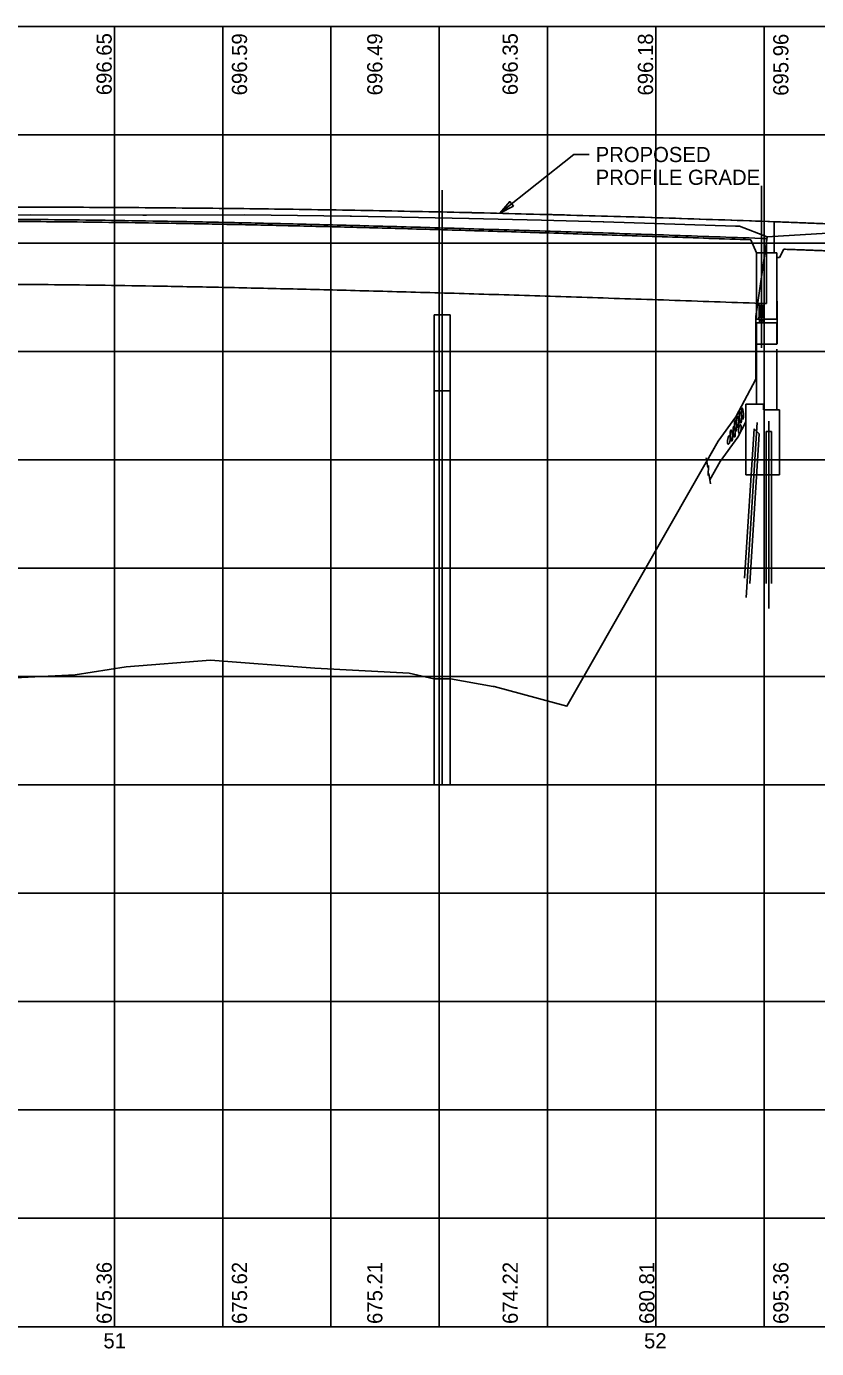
# Model space of a CAD drawing. Extents: x 991 to 1508, y 566 to 813.
# Drawn here: x 1183.7 to 1329.7, y 566 to 810 of the extents above; entities that cross this region are included whole.
import ezdxf

# ---------------------------------------------------------------- set-up
doc = ezdxf.new("R2010")
doc.units = 0
for name, color, linetype in [('BR_P_Brg_Pad_Object', 7, 'Continuous'), ('BR_P_Dia_Object', 7, 'Continuous'), ('BR_P_Gen_Approach_Slab', 7, 'Continuous'), ('BR_P_Gen_Phase_Construction', 7, 'Continuous'), ('BR_P_Gen_Waterproofing', 7, 'Continuous'), ('BR_P_Slab_Object', 7, 'Continuous'), ('BR_P_Sub_Object', 7, 'Continuous'), ('BR_X_Beam_Object', 7, 'Continuous'), ('BR_X_Brg_Centerline', 7, 'Continuous'), ('BR_X_Gen_Porous_Backfill', 7, 'Continuous'), ('BR_X_Gen_Slope_Protection', 7, 'Continuous'), ('BR_X_Sub_Const_Joint', 7, 'Continuous'), ('BR_X_Sub_Deep_Centerline', 7, 'Continuous'), ('BR_X_Sub_Deep_Object', 7, 'Continuous'), ('BR_X_Sub_Object', 7, 'Continuous'), ('Default', 7, 'Continuous'), ('PF_P_Grade_Line', 7, 'Continuous'), ('PF_P_Sta_Elev_Text', 7, 'Continuous'), ('PF_P_Text_Strip_Grades_20', 7, 'Continuous'), ('PF_X_Ground_Line', 7, 'Continuous'), ('PF_X_Text_Strip_Grade', 7, 'Continuous'), ('SC_Scratch1', 7, 'Continuous'), ('SH_Major_Grid_Line', 7, 'Continuous'), ('SH_Text', 7, 'Continuous')]:
    doc.layers.add(name, color=color, linetype=linetype)

msp = doc.modelspace()

# ---------------------------------------------------------------- linework, layer by layer
at = {"layer": 'BR_P_Brg_Pad_Object'}
for p, q in [((1320.04, 758.84), (1319.04, 758.84)), ((1319.04, 758.51), (1319.04, 758.84)), ((1320.04, 758.51), (1319.04, 758.51)), ((1319.12, 756.32), (1319.12, 758.51)), ((1319.2, 756.32), (1319.2, 758.51)), ((1319.87, 756.32), (1319.87, 758.51)), ((1319.95, 756.32), (1319.95, 758.51)), ((1320.04, 758.84), (1320.04, 758.51)), ((1320.04, 756.32), (1319.04, 756.32)), ((1319.04, 756.32), (1319.04, 755.98)), ((1320.12, 755.98), (1319.12, 755.98)), ((1319.16, 755.32), (1319.16, 755.98)), ((1319.91, 755.65), (1319.16, 755.65)), ((1319.99, 755.32), (1319.24, 755.32)), ((1319.91, 755.32), (1319.91, 755.98)), ((1320.04, 756.32), (1320.04, 755.98))]:
    msp.add_line(p, q, dxfattribs=at)
at = {"layer": 'BR_P_Dia_Object'}
for p, q in [((1318.62, 768.19), (1317.55, 770.61)), ((1318.62, 755.98), (1318.62, 768.19)), ((1321.87, 768.19), (1322.37, 768.19)), ((1322.37, 768.19), (1322.37, 755.98)), ((1318.62, 755.98), (1322.37, 755.98))]:
    msp.add_line(p, q, dxfattribs=at)
at = {"layer": 'BR_P_Gen_Approach_Slab'}
for p in [(1323.63, 768.88), (1322.37, 767.36)]:
    msp.add_line(p, (1322.87, 767.36), dxfattribs=at)
for points in [[(1321.87, 773.95), (1334.37, 773.49), (1346.87, 772.95)], [(1323.63, 768.88), (1331.31, 768.6), (1338.98, 768.28), (1346.87, 767.94)]]:
    msp.add_open_spline(points, degree=2, dxfattribs=at)
at = {"layer": 'BR_P_Gen_Phase_Construction'}
msp.add_line((1321.87, 768.19), (1318.62, 768.19), dxfattribs=at)
at = {"layer": 'BR_P_Gen_Waterproofing'}
msp.add_line((1322.45, 759.3), (1322.45, 751.33), dxfattribs=at)
at = {"layer": 'BR_P_Slab_Object'}
msp.add_line((1321.87, 773.95), (1321.87, 768.19), dxfattribs=at)
for points in [[(1030.21, 773.96), (1176.04, 779.36), (1321.87, 773.95)], [(1034.6, 770.62), (1128.92, 774.01), (1223.23, 774), (1317.55, 770.61)]]:
    msp.add_open_spline(points, degree=2, dxfattribs=at)
at = {"layer": 'BR_P_Sub_Object'}
for p, q in [((1318.62, 755.32), (1322.37, 755.32)), ((1318.62, 751.33), (1318.62, 755.32)), ((1322.37, 755.32), (1322.37, 751.33)), ((1318.62, 751.33), (1322.37, 751.33))]:
    msp.add_line(p, q, dxfattribs=at)
at = {"layer": 'BR_X_Beam_Object'}
for p, q in [((1320.45, 770.84), (1320.45, 758.84)), ((1259.04, 756.74), (1259.04, 670)), ((1262.04, 756.74), (1262.04, 670)), ((1318.63, 740.26), (1318.63, 751.33)), ((1322.38, 739.26), (1322.38, 750.46)), ((1316.63, 740.26), (1316.63, 727.26)), ((1322.88, 727.26), (1322.88, 739.26)), ((1316.42, 708.14), (1318.15, 735.75)), ((1317.39, 707.16), (1319.12, 734.78)), ((1320.38, 707.16), (1320.38, 735.26)), ((1321.38, 707.16), (1321.38, 735.26)), ((1316.63, 727.26), (1322.88, 727.26))]:
    msp.add_line(p, q, dxfattribs=at)
for points in [[(1309.43, 729.74), (1311.55, 733.44), (1314.77, 737.92), (1318.48, 744.88)], [(1316.63, 736.99), (1315.15, 734.21), (1311.92, 729.72), (1309.99, 726.34)]]:
    msp.add_lwpolyline(points, dxfattribs=at)
for points in [[(1031.63, 770.84), (1125.99, 774.38), (1220.35, 774.43), (1320.45, 770.84)], [(1031.63, 758.84), (1125.99, 762.38), (1220.35, 762.43), (1320.45, 758.84)]]:
    msp.add_open_spline(points, degree=2, dxfattribs=at)
at = {"layer": 'BR_X_Brg_Centerline'}
for p, q in [((1260.54, 670), (1260.54, 779.78)), ((1319.54, 750.66), (1319.54, 780.57))]:
    msp.add_line(p, q, dxfattribs=at)
at = {"layer": 'BR_X_Gen_Porous_Backfill'}
for points in [[(1316.17, 739.01), (1316.23, 738.41), (1316.21, 737.81), (1316.15, 737.57), (1316.05, 737.57), (1315.91, 737.99), (1315.84, 738.59), (1315.84, 739.19), (1315.9, 739.49), (1316, 739.55), (1316.11, 739.25), (1316.17, 738.95)], [(1314.86, 736.76), (1314.92, 736.16), (1314.91, 735.56), (1314.85, 735.32), (1314.74, 735.32), (1314.61, 735.74), (1314.53, 736.34), (1314.53, 736.94), (1314.59, 737.24), (1314.7, 737.3), (1314.8, 737), (1314.86, 736.7)], [(1315.26, 737.47), (1315.32, 736.87), (1315.31, 736.27), (1315.25, 736.03), (1315.14, 736.03), (1315.01, 736.45), (1314.93, 737.05), (1314.93, 737.65), (1314.99, 737.95), (1315.1, 738.01), (1315.2, 737.71), (1315.26, 737.41)], [(1315.76, 738.3), (1315.82, 737.7), (1315.81, 737.1), (1315.75, 736.86), (1315.64, 736.86), (1315.51, 737.28), (1315.43, 737.88), (1315.43, 738.48), (1315.49, 738.78), (1315.6, 738.84), (1315.7, 738.54), (1315.76, 738.24)], [(1314.1, 734.94), (1314.16, 734.34), (1314.15, 733.74), (1314.09, 733.5), (1313.98, 733.5), (1313.85, 733.92), (1313.77, 734.52), (1313.77, 735.12), (1313.83, 735.42), (1313.94, 735.48), (1314.04, 735.18), (1314.1, 734.88)], [(1314.6, 735.66), (1314.66, 735.06), (1314.65, 734.46), (1314.59, 734.22), (1314.48, 734.22), (1314.35, 734.64), (1314.27, 735.24), (1314.27, 735.84), (1314.33, 736.14), (1314.44, 736.2), (1314.54, 735.9), (1314.6, 735.6)], [(1315.64, 735.13), (1315.49, 734.89), (1315.34, 734.95), (1315.28, 735.19), (1315.28, 735.61), (1315.39, 736.15), (1315.54, 736.45), (1315.69, 736.45), (1315.76, 736.21), (1315.78, 735.79), (1315.7, 735.37), (1315.63, 735.13)], [(1313.61, 733.11), (1313.46, 732.87), (1313.31, 732.93), (1313.25, 733.17), (1313.25, 733.59), (1313.36, 734.13), (1313.51, 734.43), (1313.66, 734.43), (1313.73, 734.19), (1313.75, 733.77), (1313.67, 733.35), (1313.6, 733.11)]]:
    msp.add_lwpolyline(points, dxfattribs=at)
at = {"layer": 'BR_X_Gen_Slope_Protection'}
for p, q in [((1309.62, 728.58), (1309.33, 730.37)), ((1309.76, 728.94), (1309.62, 728.58)), ((1309.67, 727.1), (1309.76, 728.94)), ((1309.81, 727.46), (1309.67, 727.1)), ((1310.12, 725.57), (1309.81, 727.46))]:
    msp.add_line(p, q, dxfattribs=at)
at = {"layer": 'BR_X_Sub_Const_Joint'}
for p, q in [((1322.37, 755.32), (1320.62, 755.32)), ((1318.63, 740.26), (1319.88, 740.26)), ((1319.88, 740.26), (1319.88, 739.26)), ((1319.88, 739.26), (1322.38, 739.26))]:
    msp.add_line(p, q, dxfattribs=at)
at = {"layer": 'BR_X_Sub_Deep_Centerline'}
for p, q in [((1320.88, 702.59), (1320.88, 737.12)), ((1316.72, 704.61), (1318.74, 736.91))]:
    msp.add_line(p, q, dxfattribs=at)
at = {"layer": 'BR_X_Sub_Deep_Object'}
for p, q in [((1318.15, 735.75), (1319.12, 734.78)), ((1320.38, 735.26), (1321.38, 735.26))]:
    msp.add_line(p, q, dxfattribs=at)
at = {"layer": 'BR_X_Sub_Object'}
for p, q in [((1322.37, 767.21), (1322.37, 757.33)), ((1259.04, 756.74), (1262.04, 756.74)), ((1318.62, 755.32), (1320.62, 755.32)), ((1259.04, 742.74), (1262.04, 742.74)), ((1318.63, 740.26), (1316.63, 740.26)), ((1322.88, 739.26), (1322.38, 739.26))]:
    msp.add_line(p, q, dxfattribs=at)
at = {"layer": 'Default'}
msp.add_lwpolyline([(1176.04, 776.66), (1186.04, 776.65), (1196.04, 776.61), (1206.04, 776.54), (1216.04, 776.45), (1226.04, 776.34), (1236.04, 776.2), (1246.04, 776.03), (1256.04, 775.84), (1266.04, 775.63), (1276.04, 775.38), (1286.04, 775.12), (1296.04, 774.83), (1306.04, 774.51), (1316.04, 774.16), (1326.04, 773.8), (1336.04, 773.4)], dxfattribs=at)
at = {"layer": 'PF_P_Grade_Line'}
msp.add_lwpolyline([(1176.04, 776.66), (1186.04, 776.65), (1196.04, 776.61), (1206.04, 776.54), (1216.04, 776.45), (1226.04, 776.34), (1236.04, 776.2), (1246.04, 776.03), (1256.04, 775.84), (1266.04, 775.63), (1276.04, 775.38), (1286.04, 775.12), (1296.04, 774.83), (1306.04, 774.51), (1316.04, 774.16), (1326.04, 773.8), (1336.04, 773.4)], dxfattribs=at)
at = {"layer": 'PF_X_Ground_Line'}
for points in [[(1162.79, 775.17), (1184.46, 775.23), (1205.28, 775.15), (1205.94, 775.14), (1224.12, 775.23), (1243.55, 774.98), (1243.8, 774.97), (1265.46, 774.58), (1265.52, 774.58), (1278.91, 774.24), (1290.31, 773.94), (1290.39, 773.94), (1314.7, 773.16), (1315.45, 773.14), (1315.45, 773.14), (1315.45, 773.14), (1320.59, 771.15), (1320.6, 771.15), (1320.6, 771.15)], [(1177.8, 689.61), (1192.76, 690.31), (1202.16, 691.8), (1217.75, 693.03), (1237.02, 691.53), (1254.47, 690.61), (1258.98, 689.61), (1259.04, 689.6), (1259.08, 689.6), (1259.09, 689.6), (1259.18, 689.6), (1261.72, 689.6), (1261.94, 689.6), (1261.97, 689.6), (1262.03, 689.6), (1262.05, 689.6), (1262.06, 689.6), (1262.07, 689.6), (1262.09, 689.6), (1262.09, 689.6), (1269.97, 688.18), (1270.05, 688.17), (1270.13, 688.16), (1270.18, 688.15), (1283.6, 684.56), (1311.55, 733.44), (1314.77, 737.92), (1318.48, 744.88), (1318.5, 753.03), (1318.51, 756.44), (1320.59, 771.11), (1320.59, 771.11), (1320.6, 771.14), (1320.6, 771.15), (1333.77, 771.98)]]:
    msp.add_lwpolyline(points, dxfattribs=at)
at = {"layer": 'SC_Scratch1'}
msp.add_lwpolyline([(1300, 670), (1375.95, 670), (1375.95, 769.6)], dxfattribs=at)
at = {"layer": 'SH_Major_Grid_Line'}
for p, q in [((1000, 810), (1500, 810)), ((1000, 810), (1500, 810)), ((1000, 810), (1500, 810)), ((1200, 570), (1200, 810)), ((1200, 570), (1200, 810)), ((1220, 570), (1220, 810)), ((1220, 570), (1220, 810)), ((1240, 570), (1240, 810)), ((1240, 570), (1240, 810)), ((1260, 670), (1260, 810)), ((1260, 570), (1260, 810)), ((1280, 570), (1280, 810)), ((1280, 570), (1280, 810)), ((1300, 570), (1300, 810)), ((1300, 570), (1300, 810)), ((1320, 570), (1320, 810)), ((1320, 570), (1320, 810)), ((1000, 790), (1500, 790)), ((1000, 790), (1500, 790)), ((1000, 770), (1500, 770)), ((1000, 770), (1500, 770)), ((1000, 750), (1500, 750)), ((1000, 750), (1500, 750)), ((1000, 730), (1500, 730)), ((1000, 730), (1500, 730)), ((1000, 710), (1500, 710)), ((1000, 710), (1500, 710)), ((1000, 690), (1500, 690)), ((1000, 690), (1500, 690)), ((1000, 670), (1500, 670)), ((1000, 650), (1500, 650)), ((1000, 630), (1500, 630)), ((1000, 610), (1500, 610)), ((1000, 590), (1500, 590)), ((1000, 570), (1500, 570))]:
    msp.add_line(p, q, dxfattribs=at)
at = {"layer": 'SH_Text'}
for p in [(1271.19, 775.51), (1287.68, 786.35)]:
    msp.add_line(p, (1284.88, 786.35), dxfattribs=at)
msp.add_lwpolyline([(1273.74, 776.81), (1271.19, 775.51), (1273.04, 777.68)], close=True, dxfattribs=at)

# ---------------------------------------------------------------- texts
at = {"layer": 'PF_P_Sta_Elev_Text'}
for s, p in [('51', (1197.97, 566)), ('51', (1197.97, 566)), ('52', (1297.84, 566)), ('52', (1297.84, 566))]:
    msp.add_text(s, height=2.8, dxfattribs=at).set_placement(p)
at = {"layer": 'PF_P_Text_Strip_Grades_20'}
for s, p in [('696.65', (1199.5, 797.31)), ('696.65', (1199.5, 797.31)), ('696.59', (1224.5, 797.28)), ('696.59', (1224.5, 797.28)), ('696.49', (1249.5, 797.28)), ('696.49', (1249.5, 797.28)), ('696.35', (1274.5, 797.31)), ('696.35', (1274.5, 797.31)), ('696.18', (1299.5, 797.25)), ('696.18', (1299.5, 797.25)), ('695.96', (1324.5, 797.2)), ('695.96', (1324.5, 797.2))]:
    msp.add_text(s, height=2.8, rotation=90, dxfattribs=at).set_placement(p)
at = {"layer": 'PF_X_Text_Strip_Grade'}
for s, p in [('675.36', (1199.51, 570.5)), ('675.36', (1199.51, 570.5)), ('675.62', (1224.5, 570.5)), ('675.62', (1224.5, 570.5)), ('675.21', (1249.5, 570.5)), ('675.21', (1249.5, 570.5)), ('674.22', (1274.52, 570.5)), ('680.81', (1299.75, 570.5)), ('680.81', (1299.75, 570.5)), ('695.36', (1324.5, 570.5)), ('695.36', (1324.5, 570.5))]:
    msp.add_text(s, height=2.8, rotation=90, dxfattribs=at).set_placement(p)
at = {"layer": 'SH_Text'}
for s, p in [('PROPOSED ', (1288.9, 784.96)), ('PROFILE GRADE', (1288.9, 780.76))]:
    msp.add_text(s, height=2.8, dxfattribs=at).set_placement(p)

doc.saveas('drawing.dxf')
